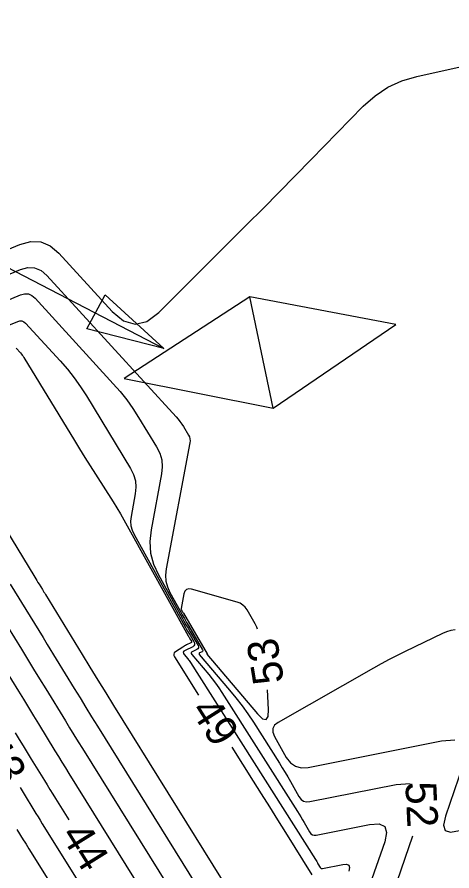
# Model space of a CAD drawing. Extents: x 2384780 to 2405861, y 547869 to 573706.
# Drawn here: x 2390249.6 to 2390277.7, y 552465.2 to 552520.5 of the extents above; entities that cross this region are included whole.
import ezdxf

# ---------------------------------------------------------------- set-up
doc = ezdxf.new("R2010")
doc.units = 0
for name, color, linetype in [('Matchline Text', 7, 'Continuous'), ('Old_Level_5', 7, 'Continuous'), ('Old_Level_60', 7, 'Continuous'), ('Old_Level_61', 7, 'Continuous')]:
    doc.layers.add(name, color=color, linetype=linetype)

# ---------------------------------------------------------------- blocks, each defined once
blk = doc.blocks.new('FALSUP')
at = {"layer": 'Matchline Text'}
for p, q in [((0, 0.07375), (-0.181, 0.00325)), ((0, -0.07375), (0, 0.07375)), ((0.1775, 0), (0, 0.07375)), ((-0.181, 0.00325), (0, -0.07375)), ((0, -0.07375), (0.1775, 0))]:
    blk.add_line(p, q, dxfattribs=at)

msp = doc.modelspace()

# ---------------------------------------------------------------- linework, layer by layer
at = {"layer": 'Old_Level_5'}
msp.add_line((2390231.61859, 552513.30112), (2390259.04813, 552499.06243), dxfattribs=at)
msp.add_lwpolyline([(2390255.24404, 552502.53981), (2390259.04813, 552499.06243), (2390254.05528, 552500.34048)], close=True, dxfattribs=at)
at = {"layer": 'Old_Level_60'}
for points in [[(2390275.42625, 552516.67825), (2390292.645, 552520.51425)], [(2390246.30825, 552504.36225), (2390249.72475, 552505.79075), (2390250.4325, 552505.9855), (2390251.09075, 552505.957), (2390251.69975, 552505.70575), (2390252.25975, 552505.23125), (2390255.70075, 552501.4655), (2390256.4425, 552500.85575), (2390257.19375, 552500.64075), (2390257.954, 552500.8205), (2390258.7235, 552501.395), (2390264.4265, 552507.08225), (2390265.47175, 552508.12825), (2390266.5135, 552509.17775), (2390267.55175, 552510.231), (2390268.58625, 552511.28775), (2390271.95975, 552514.746), (2390272.7185, 552515.4225), (2390273.54925, 552515.97), (2390274.45175, 552516.3885), (2390275.42625, 552516.67825)], [(2390247.44675, 552503.19775), (2390249.763, 552504.16625), (2390250.2425, 552504.29825), (2390250.68875, 552504.279), (2390251.10175, 552504.1085), (2390251.48125, 552503.787), (2390259.84475, 552494.63325), (2390259.97325, 552494.48575), (2390260.094, 552494.33275), (2390260.2075, 552494.174), (2390260.31325, 552494.0095), (2390260.64675, 552493.46325), (2390260.706, 552493.344), (2390260.74125, 552493.22025), (2390260.75225, 552493.092), (2390260.739, 552492.9595), (2390259.201, 552484.79475), (2390259.159, 552484.39525), (2390259.18625, 552484.007), (2390259.2825, 552483.62975), (2390259.448, 552483.26375)], [(2390248.50175, 552501.9985), (2390249.776, 552502.531), (2390250.03975, 552502.60375), (2390250.28525, 552502.593), (2390250.5125, 552502.4995), (2390250.72125, 552502.3225), (2390255.78025, 552496.7855), (2390256.22875, 552496.2705), (2390256.65075, 552495.73575), (2390257.04675, 552495.18125), (2390257.41625, 552494.607), (2390258.58075, 552492.69925), (2390258.788, 552492.28275), (2390258.91075, 552491.8505), (2390258.949, 552491.403), (2390258.9025, 552490.94025), (2390258.22225, 552487.3285), (2390258.14225, 552486.565), (2390258.19425, 552485.823), (2390258.37825, 552485.10225), (2390258.694, 552484.40275), (2390260.2265, 552481.63775), (2390260.3545, 552481.40825), (2390260.484, 552481.1795), (2390260.615, 552480.95175), (2390260.74725, 552480.72475), (2390261.26525, 552479.84175), (2390261.29875, 552479.75975), (2390261.29675, 552479.68825), (2390261.259, 552479.62775), (2390261.18575, 552479.57775), (2390260.88825, 552479.43225), (2390260.838, 552479.39825), (2390260.8155, 552479.3585), (2390260.82025, 552479.313), (2390260.8525, 552479.26175), (2390261.952, 552477.96925), (2390262.1825, 552477.6885), (2390262.40275, 552477.4005), (2390262.61275, 552477.1045), (2390262.81275, 552476.80125), (2390267.69475, 552469.102), (2390267.8075, 552468.9215), (2390267.91825, 552468.73975), (2390268.027, 552468.557), (2390268.1335, 552468.37275), (2390268.47775, 552467.76875), (2390268.56075, 552467.659), (2390268.66175, 552467.589), (2390268.78075, 552467.55875), (2390268.91775, 552467.568), (2390272.36225, 552468.252), (2390272.97725, 552468.2915), (2390273.34625, 552468.1165), (2390273.46925, 552467.727), (2390273.346, 552467.123), (2390272.24325, 552463.93825)], [(2390249.482, 552499.086), (2390249.76875, 552498.772), (2390249.8285, 552498.7035), (2390249.88475, 552498.63225), (2390249.93725, 552498.5585), (2390249.9865, 552498.482), (2390253.26325, 552493.11375), (2390253.60125, 552492.56275), (2390253.9415, 552492.0135), (2390254.2845, 552491.46575), (2390254.63, 552490.9195), (2390255.7625, 552489.13775), (2390256.00225, 552488.75425), (2390256.23625, 552488.36725), (2390256.46425, 552487.97675), (2390256.6865, 552487.58275), (2390260.6285, 552480.46975), (2390260.656, 552480.4205), (2390260.68375, 552480.37175), (2390260.71175, 552480.323), (2390260.74, 552480.2745), (2390260.833, 552480.116), (2390260.846, 552480.08425), (2390260.845, 552480.0565), (2390260.8305, 552480.033), (2390260.802, 552480.01375), (2390260.5145, 552479.873), (2390260.45325, 552479.842), (2390260.39325, 552479.809), (2390260.33425, 552479.77425), (2390260.2765, 552479.7375), (2390259.80875, 552479.43025), (2390259.729, 552479.36), (2390259.6905, 552479.281), (2390259.693, 552479.193), (2390259.73675, 552479.09625), (2390261.30275, 552476.6265)], [(2390248.42, 552487.986), (2390250.70075, 552484.257), (2390250.7685, 552484.1465), (2390250.83625, 552484.036), (2390250.90425, 552483.9255), (2390250.9725, 552483.81525), (2390251.19525, 552483.455), (2390251.24275, 552483.37775), (2390251.2905, 552483.30025), (2390251.338, 552483.223), (2390251.38525, 552483.1455), (2390253.7545, 552479.2645), (2390254.263, 552478.4335), (2390254.77325, 552477.6035), (2390255.2855, 552476.7745), (2390255.7995, 552475.94675), (2390266.35075, 552458.99625)], [(2390246.6505, 552484.74375), (2390249.83525, 552479.59225), (2390250.2285, 552478.955), (2390250.621, 552478.3175), (2390251.01225, 552477.67925), (2390251.403, 552477.0405), (2390252.67725, 552474.953), (2390252.95075, 552474.506), (2390253.22525, 552474.0595), (2390253.50075, 552473.61375), (2390253.77725, 552473.1685), (2390260.52775, 552462.32375)], [(2390249.1085, 552483.799), (2390250.40225, 552481.70625), (2390250.67925, 552481.25775), (2390250.9555, 552480.80875), (2390251.231, 552480.35925), (2390251.506, 552479.9095), (2390253.2495, 552477.05375), (2390253.6235, 552476.44225), (2390253.99925, 552475.8315), (2390254.376, 552475.2215), (2390254.75425, 552474.6125), (2390263.43925, 552460.66)], [(2390259.448, 552483.26375), (2390260.1005, 552482.086), (2390260.24125, 552481.834), (2390260.3835, 552481.583), (2390260.527, 552481.33275), (2390260.6725, 552481.0835), (2390261.562, 552479.5675), (2390261.5795, 552479.52475), (2390261.5785, 552479.4875), (2390261.55875, 552479.45575), (2390261.5205, 552479.42975), (2390261.36525, 552479.35375), (2390261.339, 552479.336), (2390261.32725, 552479.31525), (2390261.32975, 552479.2915), (2390261.3465, 552479.26475), (2390263.30875, 552476.95825), (2390263.72, 552476.45725), (2390264.113, 552475.94275), (2390264.488, 552475.415), (2390264.8445, 552474.87375), (2390266.5305, 552472.215), (2390266.71325, 552471.923), (2390266.8925, 552471.629), (2390267.06825, 552471.333), (2390267.2405, 552471.03475), (2390267.79775, 552470.0575), (2390267.932, 552469.88025), (2390268.09525, 552469.767), (2390268.28775, 552469.71775), (2390268.5095, 552469.73275), (2390274.0835, 552470.83975), (2390274.9955, 552470.898)], [(2390265.12275, 552480.89725), (2390265.07175, 552481.01725), (2390264.955, 552481.24175), (2390264.4425, 552482.141), (2390264.3195, 552482.317), (2390264.171, 552482.46025), (2390263.99625, 552482.57025), (2390263.796, 552482.64725), (2390260.847, 552483.48375), (2390260.6605, 552483.50875), (2390260.51575, 552483.466), (2390260.41325, 552483.35575), (2390260.35225, 552483.17775), (2390260.17525, 552482.23725), (2390260.17275, 552482.2135), (2390260.17425, 552482.19025), (2390260.18, 552482.16775), (2390260.18975, 552482.146)], [(2390260.18975, 552482.146), (2390260.2455, 552482.04575), (2390260.2625, 552482.01525), (2390260.27975, 552481.98475), (2390260.29725, 552481.95425), (2390260.315, 552481.924), (2390261.85875, 552479.29325), (2390261.86025, 552479.28975), (2390261.86, 552479.2865), (2390261.8585, 552479.28375), (2390261.85525, 552479.2815), (2390261.842, 552479.27525), (2390261.84, 552479.27375), (2390261.839, 552479.272), (2390261.83925, 552479.27), (2390261.8405, 552479.26775), (2390265.11625, 552475.417), (2390265.44525, 552475.0995), (2390265.67275, 552475.04), (2390265.79875, 552475.23875), (2390265.823, 552475.69525), (2390265.76575, 552476.9655)], [(2390277.8985, 552480.85925), (2390277.62025, 552480.8095), (2390277.34925, 552480.7295), (2390277.08525, 552480.619), (2390274.66225, 552479.44825), (2390274.14525, 552479.193), (2390273.63275, 552478.929), (2390273.12525, 552478.65625), (2390272.622, 552478.37475), (2390266.45475, 552474.85425), (2390266.22225, 552474.67375), (2390266.10325, 552474.46175), (2390266.09775, 552474.219), (2390266.206, 552473.94525)], [(2390249.43325, 552474.18), (2390249.69375, 552473.758), (2390249.9535, 552473.33575), (2390250.21275, 552472.91325), (2390250.4715, 552472.49025), (2390251.31525, 552471.108), (2390251.4965, 552470.812), (2390251.67825, 552470.51625), (2390251.8605, 552470.221), (2390252.04375, 552469.92625), (2390252.9, 552468.5505)], [(2390266.206, 552473.94525), (2390266.97625, 552472.5945), (2390267.241, 552472.24425), (2390267.5635, 552472.02075), (2390267.94375, 552471.9235), (2390268.3815, 552471.953), (2390277.0215, 552473.669), (2390277.89, 552473.72475)], [(2390263.44475, 552473.2485), (2390264.82975, 552471.06425), (2390265.357, 552470.23125), (2390265.8825, 552469.3975), (2390266.40675, 552468.56275), (2390266.92925, 552467.727), (2390268.634, 552464.9955)], [(2390278.4105, 552472.075), (2390277.275, 552468.795), (2390277.15, 552468.21), (2390277.262, 552467.8605), (2390277.611, 552467.74625), (2390278.19675, 552467.86775)], [(2390249.743, 552470.64425), (2390249.813, 552470.53025), (2390250.00575, 552470.21525), (2390250.63425, 552469.1855), (2390250.76925, 552468.96475), (2390250.90475, 552468.74475), (2390251.0405, 552468.52475), (2390251.177, 552468.305), (2390254.01875, 552463.73975)], [(2390249.54, 552467.94), (2390249.95325, 552467.26275), (2390250.042, 552467.11775), (2390250.131, 552466.973), (2390250.2205, 552466.8285), (2390250.31025, 552466.684), (2390252.179, 552463.68175)], [(2390275.1525, 552467.503), (2390273.891, 552463.85925)]]:
    msp.add_lwpolyline(points, dxfattribs=at)
at = {"layer": 'Old_Level_61'}
for points in [[(2390248.916, 552500.531), (2390249.59675, 552500.81575), (2390249.7375, 552500.8545), (2390249.86875, 552500.84875), (2390249.99, 552500.79875), (2390250.10175, 552500.70425), (2390252.33875, 552498.25575), (2390252.8045, 552497.72075), (2390253.243, 552497.1655), (2390253.654, 552496.5895), (2390254.038, 552495.99325), (2390256.8995, 552491.30475), (2390257.095, 552490.912), (2390257.2105, 552490.50475), (2390257.2465, 552490.083), (2390257.20275, 552489.64675), (2390256.92975, 552488.19725), (2390256.89775, 552487.891), (2390256.91875, 552487.59325), (2390256.9925, 552487.304), (2390257.11925, 552487.02325), (2390260.4275, 552481.05375), (2390260.50525, 552480.9145), (2390260.58375, 552480.77575), (2390260.66325, 552480.63725), (2390260.7435, 552480.4995), (2390261.00725, 552480.05025), (2390261.04425, 552479.95975), (2390261.042, 552479.88125), (2390261.0005, 552479.8145), (2390260.91975, 552479.7595), (2390260.41975, 552479.515), (2390260.3425, 552479.46225), (2390260.3075, 552479.401), (2390260.315, 552479.3305), (2390260.365, 552479.25125), (2390260.59725, 552478.97825), (2390260.646, 552478.919), (2390260.6925, 552478.858), (2390260.737, 552478.7955), (2390260.77925, 552478.73125), (2390268.85875, 552465.989), (2390268.902, 552465.92), (2390268.94425, 552465.85075), (2390268.98575, 552465.78075), (2390269.0265, 552465.7105), (2390269.158, 552465.47975), (2390269.1895, 552465.438), (2390269.228, 552465.41125), (2390269.2735, 552465.39975), (2390269.32575, 552465.40325), (2390270.641, 552465.6645), (2390270.876, 552465.6795), (2390271.01675, 552465.6125), (2390271.06375, 552465.464), (2390271.01675, 552465.23325)], [(2390238.8375, 552494.1585), (2390240.7835, 552491.18025), (2390241.1325, 552490.64125), (2390241.47775, 552490.1), (2390241.819, 552489.556), (2390242.156, 552489.0095), (2390243.2505, 552487.22), (2390243.48525, 552486.83675), (2390243.7205, 552486.4535), (2390243.95625, 552486.07075), (2390244.19225, 552485.68825), (2390249.63425, 552476.886), (2390249.96125, 552476.3565), (2390250.28725, 552475.82675), (2390250.6125, 552475.29625), (2390250.93725, 552474.7655), (2390251.99625, 552473.0305), (2390252.2235, 552472.659), (2390252.45175, 552472.288), (2390252.68075, 552471.9175), (2390252.9105, 552471.54725), (2390257.69825, 552463.85575)]]:
    msp.add_lwpolyline(points, dxfattribs=at)

# ---------------------------------------------------------------- block references
at = {"layer": 'Matchline Text', "xscale": 50, "yscale": 50, "rotation": 11.778945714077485}
msp.add_blockref('FALSUP', (2390265.37925, 552498.8035), dxfattribs=at)

# ---------------------------------------------------------------- texts
at = {"layer": 'Old_Level_60'}
for s, rotation, p in [('53', 99.287553, (2390266.83875, 552477.49275)), ('49', 302.379217, (2390260.7365, 552475.652)), ('43', 301.699478, (2390247.0105, 552473.1675)), ('52', 272.648692, (2390274.6815, 552470.98875)), ('44', 301.900831, (2390252.32575, 552467.581))]:
    msp.add_text(s, height=2, rotation=rotation, dxfattribs=at).set_placement(p)

doc.saveas('drawing.dxf')
